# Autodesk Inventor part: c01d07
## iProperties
Created: 2004-05
Part Number: c01d07
Document SubType Name: Modeling
Designer: CADCIM Technologies
Manufacturer: Standard
Standards Organization: Custom
Author: CADCIM Technologies
